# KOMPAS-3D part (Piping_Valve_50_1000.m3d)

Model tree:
1. Plane XY
2. Plane ZX
3. Plane ZY
4. X Axis
5. Y Axis
6. Z Axis
7. Origin
8. Sketch:1
9. Extrude:1  (labels: На расстояние 1; На расстояние 2)
     Толщина стенки 1 = 1; Толщина стенки 2 = 1; Расстояние 2 = 10
10. Sketch:5
11. Extrude:2  (labels: На расстояние 1; На расстояние 2)
     Толщина стенки 1 = 1; Толщина стенки 2 = 1; Угол 1 = 45; Расстояние 2 = 10
12. Sketch:7
13. Cut-Extrude:2  (labels: На расстояние 1)
     Толщина стенки 1 = 1; Толщина стенки 2 = 1; Расстояние 1 = 10; Расстояние 2 = 9
14. Intersection Axis of Two Planes:1
15. Circular Pattern:1  (labels: Экземпляр ( 1, 2 );; Вырезать элемент выдавливания:2; Экземпляр ( 1, 3 );; Вырезать элемент выдавливания:2)
     N 1 = 1; Шаг 1 = 10; Шаг 2 = 360
16. Sketch:6
17. Cut-Extrude:1  (labels: На расстояние 1; На расстояние 2)
     Толщина стенки 1 = 1; Толщина стенки 2 = 1; Расстояние 1 = 9; Расстояние 2 = 3
18. Sketch:8
19. Attachment Point:1
20. Sketch:10
21. Parallel Plane:1
22. Sketch:12
23. Sketch:11
24. Revolve:1
     Толщина стенки 1 = 1; Толщина стенки 2 = 1; Угол 1 = 360; Угол 2 = 360
25. Mirror Body:2
26. Attachment Point:2
27. Sketch:13
28. Extrude:3  (labels: На расстояние 2)
     Толщина стенки 1 = 1; Толщина стенки 2 = 1; Расстояние 1 = 378; Расстояние 2 = 10
29. Sketch:15
30. Revolve:2
     Толщина стенки 1 = 1; Толщина стенки 2 = 1; Угол 1 = 360; Угол 2 = 360
31. Plane at Angle:1
     Угол = 45
32. Sketch:16
33. Extrude:4  (labels: На расстояние 2)
     Толщина стенки 1 = 1; Толщина стенки 2 = 1; Расстояние 1 = 1; Расстояние 2 = 10
34. Circular Pattern:2  (labels: Экземпляр ( 1, 2 );; Операция выдавливания:4; Экземпляр ( 1, 3 );; Операция выдавливания:4)
     N 1 = 1; Шаг 1 = 10; N 2 = 4; Шаг 2 = 360
35. Control point:1

Expressions: (Dm-Dn)*1.25; (Dn-d1)*0.5-1; Dm*0.5; D*0.075; Lz*0.4; D*0.05; D1z*1.3; Hmax*0.8
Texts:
  Valve Dn 50
  Three Point Plane
  Plane at Angle
  Line and Point Plane
  Axis through Two Vertices
  Axis of Feature
  Axis of Conical Surface
  Axis through Edge
  Приклеить элемент выдавливания
  Приклеить элемент вращения
  Приклеить кинематический элемент
  Приклеить элемент по сечениям
  Trim by Surface
  Trim by Sketch
  Feature with No History
  Intersection Axis of Two Planes
  Two Line Plane
  Line and Face Plane
  Bend by line
  Hole in sheet body
  Cut in sheet body
  Point in CM
  Linear Dimension from Line to Point
  Surface Finish Symbol
  Geometric Tolerance Symbol
  Текст на чертеже
  Линия-выноска #1
  Линия-выноска #2
  Линия-выноска #3
  Отклонения формы и база
  Марка координационной оси
  Марка/позиционное обозначение с линией-выноской
  Марка/позиционное обозначение на линии
  Марка/позиционное обозначение без линии-выноски
  Dm05
  Экземпляр ( 1, 2 );
  Экземпляр ( 1, 3 );
  Экземпляр ( 1, 4 );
